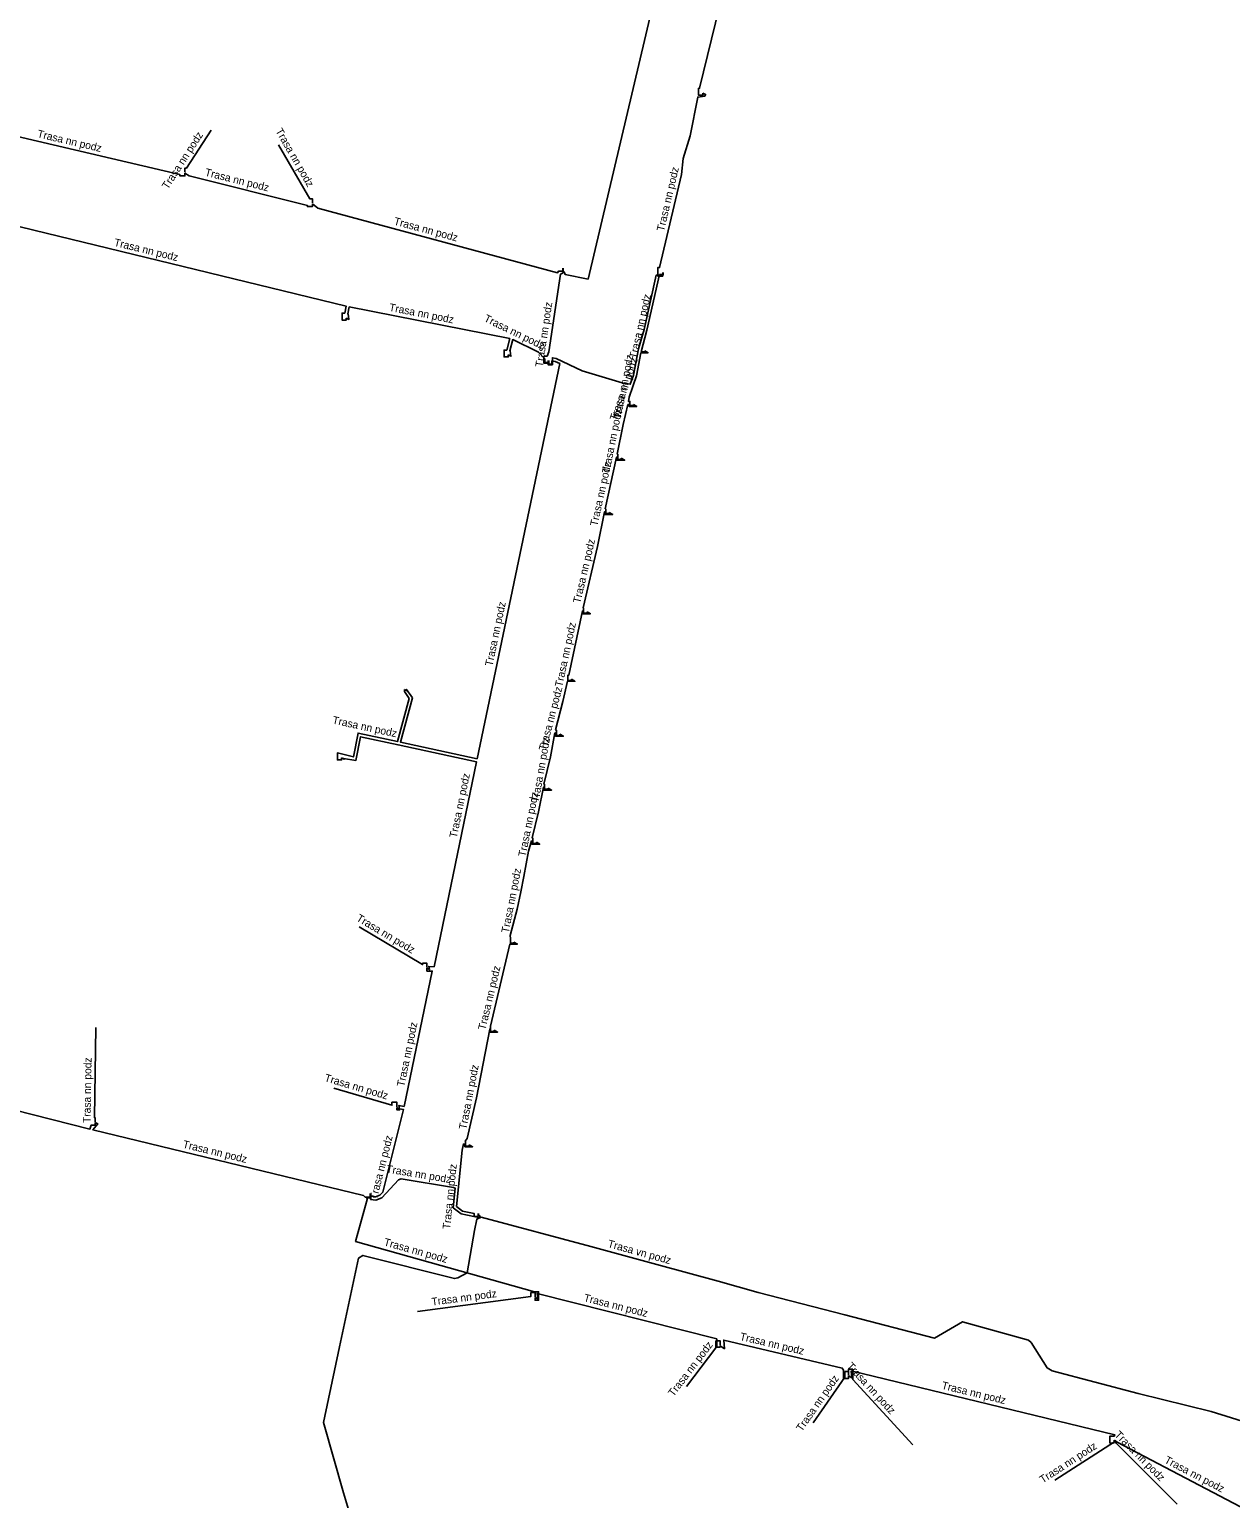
# Model space of a CAD drawing. Extents: x -742082 to -717476, y -1040737 to -1024597.
# Drawn here: x -735762.9 to -735606.4, y -1032117.1 to -1031925.7 of the extents above; entities that cross this region are included whole.
import ezdxf

# ---------------------------------------------------------------- set-up
doc = ezdxf.new("R2010")
doc.units = 0
for name, color, linetype in [('Level 15', 7, 'Continuous'), ('Level 20', 7, 'Continuous'), ('Level 25', 7, 'Continuous')]:
    doc.layers.add(name, color=color, linetype=linetype)

msp = doc.modelspace()

# ---------------------------------------------------------------- linework, layer by layer
at = {"layer": 'Level 15'}
for points in [[(-735707.5, -1031870.46), (-735707.5, -1031871.03), (-735706.96, -1031871.03), (-735706.96, -1031870.42), (-735703.62, -1031872.34), (-735701.82, -1031873.59), (-735678.97, -1031902.19), (-735678.89, -1031903.21), (-735681.36, -1031913.53), (-735680.81, -1031914.7), (-735680.03, -1031915.49), (-735690.1, -1031958.2), (-735693.07, -1031957.63), (-735693.23, -1031957.26), (-735693.39, -1031957.26), (-735693.39, -1031956.79)], [(-735707.43, -1031870.46), (-735707.43, -1031870.73), (-735707.26, -1031870.73), (-735707.26, -1031870.3), (-735706.91, -1031870.23), (-735706.53, -1031870.21), (-735703.41, -1031872), (-735701.54, -1031873.29), (-735678.58, -1031902.04), (-735678.48, -1031903.24), (-735680.94, -1031913.49), (-735680.47, -1031914.47), (-735679.71, -1031915.25), (-735679.12, -1031915.23), (-735672.3, -1031916.62), (-735672.06, -1031916.78), (-735671.92, -1031917.37), (-735673.53, -1031924.83), (-735675.59, -1031933.35), (-735675.71, -1031933.35), (-735675.71, -1031934.26), (-735675.16, -1031934.26), (-735675.16, -1031934)], [(-735675.16, -1031934), (-735674.8, -1031934.16), (-735674.89, -1031934.36), (-735675.83, -1031934.49), (-735676.81, -1031939.55), (-735677.71, -1031942.51), (-735677.96, -1031944.6), (-735680.8, -1031956.71), (-735681.03, -1031956.71), (-735681.03, -1031957.82), (-735680.37, -1031957.82), (-735680.37, -1031957.35)], [(-735768.6, -1031938.1), (-735768.25, -1031938.26), (-735768.68, -1031938.56), (-735768.7, -1031938.65), (-735743.25, -1031944.59), (-735743.25, -1031944.76), (-735742.6, -1031944.76), (-735742.6, -1031944.4)], [(-735742.6, -1031944.29), (-735742.6, -1031943.75), (-735742.41, -1031943.75), (-735739.2, -1031938.8)], [(-735726, -1031948.29), (-735726, -1031947.75), (-735726.36, -1031947.75), (-735730.4, -1031940.7)], [(-735742.6, -1031944.4), (-735742.05, -1031944.76), (-735726.65, -1031948.61), (-735726.65, -1031948.76), (-735726, -1031948.76), (-735726, -1031948.4)], [(-735726, -1031948.4), (-735725.28, -1031948.95), (-735694.09, -1031957.4), (-735693.95, -1031957.16), (-735693.37, -1031957.16), (-735693.37, -1031956.79)], [(-735769.9, -1031953.9), (-735769.55, -1031954.06), (-735769.65, -1031953.35), (-735769.7, -1031953.35), (-735768.91, -1031950.25), (-735721.59, -1031961.75), (-735721.8, -1031962.65), (-735722.15, -1031962.65), (-735722.15, -1031963.56), (-735721.6, -1031963.56), (-735721.6, -1031963.3)], [(-735693.34, -1031956.79), (-735693.34, -1031957.38), (-735693.7, -1031957.57), (-735695.2, -1031967.68), (-735695.44, -1031968.27), (-735695.85, -1031968.27), (-735695.85, -1031969.18), (-735695.23, -1031969.18), (-735695.23, -1031968.81)], [(-735695.31, -1031968.81), (-735695.31, -1031969.38), (-735694.74, -1031969.38), (-735694.74, -1031968.45), (-735694.25, -1031968.55), (-735690.89, -1031970.15), (-735685.24, -1031971.86), (-735684.61, -1031971.92), (-735684.2, -1031970.73), (-735683.53, -1031967.3), (-735682.82, -1031964.77), (-735681.24, -1031957.72), (-735680.93, -1031957.72), (-735680.35, -1031957.72), (-735680.35, -1031957.35)], [(-735680.32, -1031957.35), (-735680.32, -1031957.62), (-735680.8, -1031957.62), (-735682.44, -1031964.87), (-735683.18, -1031967.7), (-735682.73, -1031967.7), (-735682.73, -1031967.54)], [(-735721.6, -1031963.3), (-735721.25, -1031963.46), (-735721.34, -1031962.75), (-735721.41, -1031962.75), (-735721.2, -1031961.84), (-735700.3, -1031965.96), (-735700.69, -1031967.45), (-735701.05, -1031967.45), (-735701.05, -1031968.36), (-735700.5, -1031968.36), (-735700.5, -1031968.1)], [(-735700.5, -1031968.1), (-735700.15, -1031968.26), (-735700.24, -1031967.55), (-735700.3, -1031967.55), (-735699.92, -1031966.09), (-735696.54, -1031967.74), (-735695.75, -1031968.59), (-735695.75, -1031969.08), (-735695.21, -1031969.08), (-735695.21, -1031968.81)], [(-735695.28, -1031968.81), (-735695.28, -1031969.28), (-735694.84, -1031969.28), (-735694.84, -1031968.94), (-735694.81, -1031968.85), (-735694.38, -1031968.93), (-735693.8, -1031969.21), (-735704.56, -1032020.7), (-735714.55, -1032018.55), (-735712.98, -1032012.76), (-735713.74, -1032011.66), (-735713.65, -1032011.86), (-735714, -1032011.7)], [(-735682.73, -1031967.54), (-735682.28, -1031967.8), (-735683.22, -1031967.8), (-735683.82, -1031970.83), (-735684.76, -1031973.58), (-735684.84, -1031974.16), (-735684.66, -1031974.15), (-735684.66, -1031974.7), (-735684.21, -1031974.7), (-735684.21, -1031974.54)], [(-735684.21, -1031974.54), (-735683.76, -1031974.8), (-735684.76, -1031974.8), (-735684.76, -1031974.56), (-735684.92, -1031974.57), (-735685.55, -1031977.17), (-735686.31, -1031981.01), (-735686.23, -1031981.04), (-735686.23, -1031981.72), (-735685.78, -1031981.72), (-735685.78, -1031981.56)], [(-735685.78, -1031981.56), (-735685.33, -1031981.82), (-735686.33, -1031981.82), (-735686.33, -1031981.43), (-735686.4, -1031981.41), (-735687.87, -1031988.13), (-735687.8, -1031988.15), (-735687.8, -1031988.77), (-735687.35, -1031988.77), (-735687.35, -1031988.61)], [(-735687.35, -1031988.61), (-735686.9, -1031988.87), (-735687.9, -1031988.87), (-735687.9, -1031988.53), (-735687.95, -1031988.53), (-735688.87, -1031993.05), (-735690.73, -1032001.05), (-735690.69, -1032001.06), (-735690.69, -1032001.72), (-735690.24, -1032001.72), (-735690.24, -1032001.56)], [(-735690.24, -1032001.56), (-735689.79, -1032001.82), (-735690.79, -1032001.82), (-735690.79, -1032001.45), (-735690.82, -1032001.44), (-735692.61, -1032009.8), (-735692.72, -1032009.8), (-735692.72, -1032010.5), (-735692.27, -1032010.5), (-735692.27, -1032010.34)], [(-735692.27, -1032010.34), (-735691.82, -1032010.6), (-735692.79, -1032010.6), (-735693.38, -1032013.24), (-735694.34, -1032016.95), (-735694.22, -1032016.99), (-735694.22, -1032017.68), (-735693.77, -1032017.68), (-735693.77, -1032017.52)], [(-735714, -1032011.7), (-735714, -1032011.96), (-735714.03, -1032011.96), (-735713.42, -1032012.84), (-735714.94, -1032018.46), (-735720.06, -1032017.36), (-735720.66, -1032020.47), (-735722.75, -1032019.95), (-735722.75, -1032020.86), (-735722.2, -1032020.86), (-735722.2, -1032020.6)], [(-735722.2, -1032020.6), (-735721.85, -1032020.76), (-735721.95, -1032020.66), (-735720.34, -1032020.93), (-735719.74, -1032017.84), (-735714.84, -1032018.9), (-735704.64, -1032021.1), (-735710.16, -1032047.8), (-735710.85, -1032047.75), (-735710.75, -1032048.16), (-735711.1, -1032048)], [(-735693.77, -1032017.52), (-735693.32, -1032017.78), (-735694.32, -1032017.78), (-735694.32, -1032017.38), (-735694.43, -1032017.34), (-735694.98, -1032020.46), (-735695.85, -1032024.01), (-735695.77, -1032024.03), (-735695.77, -1032024.68), (-735695.32, -1032024.68), (-735695.32, -1032024.52)], [(-735695.32, -1032024.52), (-735694.86, -1032024.78), (-735695.87, -1032024.78), (-735695.87, -1032024.41), (-735695.91, -1032024.4), (-735696.55, -1032027.61), (-735697.37, -1032031.01), (-735697.3, -1032031.04), (-735697.3, -1032031.04), (-735697.3, -1032031.75), (-735696.84, -1032031.75), (-735696.84, -1032031.59)], [(-735696.84, -1032031.59), (-735696.39, -1032031.85), (-735697.4, -1032031.85), (-735697.4, -1032031.43), (-735697.47, -1032031.4), (-735697.85, -1032032.74), (-735698.49, -1032036.06), (-735698.87, -1032038.02), (-735699.35, -1032040.29), (-735700.27, -1032043.71), (-735700.22, -1032044.14), (-735700.22, -1032044.75), (-735699.77, -1032044.75), (-735699.77, -1032044.59)], [(-735711.1, -1032047.89), (-735711.1, -1032047.35), (-735711.65, -1032047.35), (-735711.65, -1032047.53), (-735719.9, -1032042.6)], [(-735699.77, -1032044.59), (-735699.31, -1032044.85), (-735700.28, -1032044.85), (-735702.83, -1032055.54), (-735702.8, -1032055.55), (-735702.8, -1032056.22), (-735702.35, -1032056.22), (-735702.35, -1032056.06)], [(-735711.1, -1032048), (-735711.1, -1032048.36), (-735710.4, -1032048.36), (-735714.06, -1032066), (-735714.74, -1032065.87), (-735714.65, -1032066.36), (-735715, -1032066.2)], [(-735754.3, -1032067.99), (-735754.3, -1032067.45), (-735754.39, -1032067.45), (-735754.2, -1032055.7)], [(-735702.35, -1032056.06), (-735701.9, -1032056.32), (-735702.9, -1032056.32), (-735702.9, -1032055.93), (-735702.91, -1032055.93), (-735704.65, -1032064.86), (-735705.86, -1032070.19), (-735706.12, -1032070.51), (-735706.05, -1032070.52), (-735706.05, -1032071.16), (-735705.6, -1032071.16), (-735705.6, -1032071)], [(-735754.3, -1032068.1), (-735754.3, -1032068.46), (-735754.82, -1032068.46), (-735754.99, -1032068.95), (-735787.31, -1032060.75), (-735786.65, -1032059.96), (-735787, -1032059.8)], [(-735715, -1032066.09), (-735715, -1032065.45), (-735715.65, -1032065.45), (-735715.65, -1032065.84), (-735723.2, -1032063.6)], [(-735715, -1032066.2), (-735715, -1032066.46), (-735714.65, -1032066.46), (-735714.65, -1032066.3), (-735714.15, -1032066.39), (-735716.83, -1032077.15), (-735717.21, -1032077.55), (-735717.81, -1032077.79), (-735718.1, -1032077.76), (-735718.11, -1032077.7), (-735718.43, -1032077.7), (-735718.43, -1032077.33)], [(-735718.45, -1032077.33), (-735718.45, -1032077.8), (-735719.12, -1032077.8), (-735719.36, -1032077.6), (-735754.6, -1032069.05), (-735753.95, -1032068.26), (-735754.3, -1032068.1)], [(-735705.6, -1032071), (-735705.15, -1032071.26), (-735706.15, -1032071.26), (-735706.15, -1032070.91), (-735706.31, -1032070.88), (-735706.5, -1032071.7), (-735707.25, -1032079.02), (-735706.48, -1032079.63), (-735704.96, -1032079.94), (-735704.96, -1032080.32), (-735704.4, -1032080.32), (-735704.4, -1032079.95)], [(-735704.37, -1032079.95), (-735704.37, -1032080.22), (-735704.23, -1032080.22), (-735704.18, -1032080.5), (-735706.65, -1032080.01), (-735707.67, -1032079.2), (-735707.41, -1032076.65), (-735707.61, -1032076.58), (-735714.43, -1032075.44), (-735714.8, -1032075.57), (-735716.98, -1032077.89), (-735717.75, -1032078.2), (-735718.44, -1032078.12), (-735718.4, -1032078), (-735718.4, -1032077.33)], [(-735718.48, -1032077.33), (-735718.48, -1032077.9), (-735718.92, -1032077.9), (-735718.88, -1032078.12), (-735720.38, -1032083.59), (-735697.09, -1032090.15), (-735697.09, -1032090.15), (-735696.55, -1032090.15), (-735696.55, -1032091.26), (-735697, -1032091.26), (-735697, -1032090.9)], [(-735697, -1032090.79), (-735697, -1032090.25), (-735697.55, -1032090.25), (-735697.55, -1032090.76), (-735712.3, -1032092.7)], [(-735697, -1032090.9), (-735696.65, -1032091.06), (-735696.74, -1032090.35), (-735673.35, -1032096.28), (-735673.35, -1032097.36), (-735672.9, -1032097.35), (-735672.9, -1032097.2)], [(-735672.9, -1032097.09), (-735672.9, -1032096.55), (-735673.45, -1032096.55), (-735673.45, -1032097.46), (-735677.3, -1032102.5)], [(-735672.9, -1032097.2), (-735672.35, -1032097.56), (-735672.44, -1032096.45), (-735657.01, -1032100.08), (-735656.85, -1032100.35), (-735656.85, -1032101.46), (-735656.2, -1032101.46), (-735656.2, -1032101.1)], [(-735656.19, -1032100.99), (-735656.19, -1032100.55), (-735656.65, -1032100.55), (-735656.65, -1032101.26), (-735660.8, -1032107.2)], [(-735656.21, -1032100.99), (-735656.21, -1032100.25), (-735655.64, -1032100.25), (-735655.64, -1032101.56), (-735647.8, -1032110.1)], [(-735656.2, -1032101.1), (-735655.75, -1032101.36), (-735655.84, -1032100.45), (-735621.5, -1032108.8), (-735621.55, -1032108.95), (-735622.15, -1032108.95), (-735622.15, -1032109.86), (-735621.7, -1032109.86), (-735621.59, -1032109.76), (-735621.59, -1032109.49)], [(-735621.57, -1032109.49), (-735621.57, -1032109.68), (-735629.3, -1032114.7)], [(-735621.57, -1032109.49), (-735621.21, -1032109.76), (-735598, -1032121.9)], [(-735621.57, -1032109.49), (-735621.33, -1032109.86), (-735613.4, -1032117.8)]]:
    msp.add_lwpolyline(points, dxfattribs=at)
at = {"layer": 'Level 25'}
msp.add_lwpolyline([(-735720.79, -1032120.26), (-735721.94, -1032116.34), (-735724.57, -1032107.16), (-735722.49, -1032097.3), (-735719.99, -1032085.75), (-735719.42, -1032085.42), (-735707.52, -1032088.43), (-735707.06, -1032088.34), (-735705.83, -1032087.68), (-735704.88, -1032082.15), (-735704.6, -1032080.67), (-735704.04, -1032080.43), (-735689.76, -1032084.24), (-735681.16, -1032086.61), (-735673.18, -1032088.75), (-735667.96, -1032090.23), (-735656.67, -1032093.13), (-735644.99, -1032096.21), (-735641.33, -1032094.05), (-735632.76, -1032096.46), (-735632.38, -1032096.77), (-735630.32, -1032100.07), (-735629.67, -1032100.46), (-735618.47, -1032103.38), (-735608.96, -1032105.73), (-735603.65, -1032107.38)], dxfattribs=at)

# ---------------------------------------------------------------- texts
at = {"layer": 'Level 20'}
for s, rotation, p in [('Trasa nn podz', 299.8271, (-735730.85, -1031938.91)), ('Trasa nn podz', 346.8452, (-735761.9, -1031939.72)), ('Trasa nn podz', 57.051, (-735744.84, -1031946.59)), ('Trasa nn podz', 345.9476, (-735740.08, -1031944.73)), ('Trasa nn podz', 76.8201, (-735680.22, -1031952.06)), ('Trasa nn podz', 344.8442, (-735715.47, -1031951.09)), ('Trasa nn podz', 346.3317, (-735751.91, -1031953.87)), ('Trasa nn podz', 348.8452, (-735716.08, -1031962.34)), ('Trasa nn podz', 81.5585, (-735696.01, -1031969.73)), ('Trasa nn podz', 77.3093, (-735683.79, -1031968.63)), ('Trasa nn podz', 333.9853, (-735703.75, -1031963.66)), ('Trasa nn podz', 71.0302, (-735686.38, -1031976.74)), ('Trasa nn podz', 78.8957, (-735685.85, -1031976.54)), ('Trasa nn podz', 78.7554, (-735687.33, -1031983.58)), ('Trasa nn podz', 77.6419, (-735688.89, -1031990.47)), ('Trasa nn podz', 76.8935, (-735691.12, -1032000.52)), ('Trasa nn podz', 78.1939, (-735702.56, -1032008.71)), ('Trasa nn podz', 77.8619, (-735693.47, -1032011.41)), ('Trasa nn podz', 75.4573, (-735695.58, -1032019.72)), ('Trasa nn podz', 347.8285, (-735723.47, -1032016.11)), ('Trasa nn podz', 79.9473, (-735696.55, -1032026.46)), ('Trasa nn podz', 78.3247, (-735707.21, -1032031.08)), ('Trasa nn podz', 78.7253, (-735698.24, -1032033.53)), ('Trasa nn podz', 79.0004, (-735700.44, -1032043.47)), ('Trasa nn podz', 329.133, (-735720.37, -1032041.74)), ('Trasa nn podz', 76.5857, (-735703.48, -1032056.11)), ('Trasa nn podz', 78.2714, (-735714.05, -1032063.49)), ('Trasa nn podz', 89.0608, (-735754.9, -1032068.17)), ('Trasa nn podz', 79.0129, (-735705.97, -1032069.06)), ('Trasa nn podz', 343.4955, (-735724.51, -1032062.69)), ('Trasa nn podz', 346.3619, (-735742.96, -1032071.36)), ('Trasa nn podz', 75.9804, (-735717.61, -1032078.21)), ('Trasa nn podz', 350.4668, (-735716.44, -1032074.59)), ('Trasa nn podz', 84.1339, (-735708.07, -1032082.04)), ('Trasa nn podz', 344.2844, (-735716.78, -1032084.09)), ('Trasa vn podz', 344.5646, (-735687.62, -1032084.31)), ('Trasa nn podz', 7.4959, (-735710.43, -1032091.95)), ('Trasa nn podz', 345.7669, (-735690.74, -1032091.36)), ('Trasa nn podz', 346.7515, (-735670.41, -1032096.41)), ('Trasa nn podz', 52.6297, (-735678.98, -1032103.88)), ('Trasa nn podz', 312.5596, (-735656.49, -1032099.9)), ('Trasa nn podz', 55.0643, (-735662.27, -1032108.44)), ('Trasa nn podz', 346.3344, (-735644.13, -1032102.78)), ('Trasa nn podz', 314.9515, (-735621.61, -1032108.87)), ('Trasa nn podz', 33.0121, (-735630.9, -1032115.14)), ('Trasa nn podz', 332.3864, (-735615.14, -1032112.37))]:
    msp.add_text(s, height=1, rotation=rotation, dxfattribs=at).set_placement(p)

doc.saveas('drawing.dxf')
